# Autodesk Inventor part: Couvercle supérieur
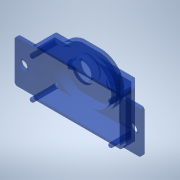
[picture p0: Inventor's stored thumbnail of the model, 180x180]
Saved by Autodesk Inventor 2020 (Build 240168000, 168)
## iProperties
Created: 2002-01
Part Number: Couvercle supérieur
Material: Polycarbonate, fumée
Document SubType Name: Modélisation
Designer: Philippe
Density: 1.2 g/cm^3
Appearance: Bleu (transparent)
Mass: 0.518225 g
Surface Area: 14.83 cm^2
Volume: 0.431854 cm^3
Control State: 0
Master: False
Checked Out: False
Shininess: 20.0
Angle Display Precision: 2
Document Length Units: 11269
Document Angle Units: 11279
Document Time Units: 11290
Document Mass Units: 11283
Document Length Units Precision: 3
Document Angle Units Precision: 2
Density: 0.0
Volumn: 0.0
Area: 0.0
PropertySet Name: Model Information
Author: Philippe
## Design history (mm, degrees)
sketch "Esquisse1"
  geometry: L1 (-1.506, 0)-(28.494, 0); L2 (28.494, 0)-(28.494, 0.8); L3 (28.494, 0.8)-(23.994, 0.8); L4 (23.994, 0.8)-(23.994, 5); L5 (23.994, 5)-(2.994, 5); L6 (2.994, 5)-(2.994, 0.8); L7 (2.994, 0.8)-(-1.506, 0.8); L8 (-1.506, 0.8)-(-1.506, 0); L9 (2.994, 0.8)-(2.994, 0); L10 (23.994, 0.8)-(23.994, 0)
  constraints: 20 end point, 8 parallel, 2 point on line, 1 collinear, 1 horizontal, 1 perpendicular, 1 other
  dimensions: "d0" = 4.5 distance of L2.end L3.end; "d1" = 4.5 distance of L6.end L7.end (= d0); "d2" = 30 distance of L1.start L1.end; "d3" = 0.8 distance between parallel lines of L3 L1; "d4" = 5 distance between parallel lines of L5 L1
extrude "Extrusion1" new body sketch "Esquisse1" stored distance "d5" = 11.4; taper "d6" = 0 deg
extrude "Extrusion2" join sketch "Esquisse1" stored distance "d7" = 10; taper "d8" = 0 deg
fillet "Congé1" dims "d9" = 0.6
fillet "Congé2" dims "d10" = 0.6
chamfer "Chanfrein1" distance "d11" = 2; stored, may be unused: second distance "d12" = 2, angle "d81" = 45 deg
sketch "Esquisse2"
  geometry: L1 (19, 10.8)-(0.6, 10.8) reference; L2 (0, 10.2)-(0, 0) reference; L3 (0.6, -0.6)-(19, -0.6) reference; A1 r 5.8 centre (5.8, 5.1) between (4.728, 10.8) and (4.728, -0.6); A2 r 5.7 centre (8.9, 5.1) between (8.9, -0.6) and (8.9, 10.8)
  constraints: 4 point on circle, 4 point on line, 3 tangent, 2 centre point, 1 horizontal alignment
  dimensions: "d13" = 5.8 radius of A1; "d14" = 14.6 dimension on A2 A1
extrude "Extrusion3" join sketch "Esquisse2" distance "d15" = 2.2; taper "d16" = 0 deg
fillet "Congé3" dims "d17" = 0.5
feature "Coque1" dims "d18" = 0.6, "d19" = 0.8
sketch "Esquisse3"
  geometry: C1 r 2.6 at (5.8, 5.1); A1 r 5.3 centre (5.8, 5.1) between (4.775, 10.3) and (4.775, -0.1) reference
  constraints: 1 centre point, 1 coincident
  dimensions: "d20" = 5.2 diameter of C1
extrude "Extrusion4" join sketch "Esquisse3" distance "d21" = 0.3; taper "d22" = 0 deg
sketch "Esquisse5"
  geometry: C1 r 2.6 at (1.015, -5.1); C2 r 2.6 at (1.015, -5.1) reference; A1 r 5.2 centre (1.015, -5.1) between (0, 0) and (0, -10.2) reference
  constraints: 1 centre point, 1 coincident, 1 concentric
extrude "Extrusion5" join sketch "Esquisse5" distance "d23" = 0.7; taper "d24" = 0 deg
sketch "Esquisse6"
  geometry: C1 r 2.6 at (0, 0) reference; 1 further point
  constraints: 1 coincident
hole "Perçage1" sketch "Esquisse6" at (0, 0), (0, 0) diameter "d25" = 4; stored, may be unused: countersink angle "d29" = 82 deg, drill point angle "d31" = 118 deg; dims "d26" = 6, "d27" = 4, "d28" = 2, "d30" = 8
sketch "Esquisse8"
  geometry: L1 (0, 11.4)-(0, 0) reference; L2 (-18.4, 0.6)-(1.4, 0.6) reference; L3 (1.4, 10.8)-(-18.4, 10.8) reference; L4 (-1, 0.6)-(-3.5, 0.6); L5 (-3.5, 0.6)-(-3.5, 10.8); L6 (-3.5, 10.8)-(-1, 10.8); L7 (-1, 10.8)-(-1, 0.6)
  constraints: 8 end point, 2 parallel, 2 point on line, 1 horizontal, 1 perpendicular
  dimensions: "d41" = 2.5 distance between parallel lines of L5 L7; "d42" = 1 distance between parallel lines of L1 L7
extrude "Extrusion6" cut sketch "Esquisse8" distance "d43" = 0.2; taper "d44" = 0 deg
sketch "Esquisse9"
  geometry: C1 r 2.6 at (1.015, -5.1) reference; C2 r 1 at (7.015, -5.1); C3 r 0.5 at (7.015, -5.1)
  constraints: 2 centre point, 1 coincident, 1 horizontal alignment
  dimensions: "d45" = 6 distance of C1.centre C2.centre; "d46" = 2 diameter of C2; "d47" = 1 diameter of C3
extrude "Extrusion7" join sketch "Esquisse9" distance "d48" = 0.3; taper "d49" = 0 deg
sketch "Esquisse10"
  geometry: L1 (4.115, -10.2)-(0, -10.2) reference; L2 (-2.076, -4.272)-(-0.917, -4.582); L3 (-2.076, -5.928)-(-1.497, -5.773); L4 (1.015, -5.1)-(-3.261, -5.1); L5 (-0.917, -4.582)-(-1.497, -4.427); L6 (-1.497, -5.773)-(-0.917, -5.618); A1 r 5.2 centre (1.015, -5.1) between (0, 0) and (0, -10.2) reference; A2 r 3.2 centre (1.015, -5.1) between (-2.076, -4.272) and (-2.076, -5.928); A3 r 2 centre (1.015, -5.1) between (-0.917, -4.582) and (-0.917, -5.618) reference; A4 r 2.6 centre (1.015, -5.1) between (-1.497, -5.773) and (-1.497, -4.427) reference; 1 further point
  constraints: 10 end point, 6 point on circle, 2 point on line, 1 centre point, 1 collinear, 1 concentric, 1 midpoint, 1 parallel, 3 other
  dimensions: "d50" = 3.2 radius of A2; "d51" = 30 deg angle of L3 L2
extrude "Extrusion8" join sketch "Esquisse10" distance "d52" = 1.2; taper "d53" = 0 deg
node "Plan de construction1"
sketch "Esquisse12"
  geometry: L1 (-0.6, -10.6)-(-0.6, -0.6) reference; L2 (20.4, -0.6)-(20.4, -10.6) reference; L3 (0, -11.4)-(19.8, -11.4) reference; L4 (19.8, 0)-(0, 0) reference; C1 r 0.5 at (0.6, -1.2); C2 r 0.5 at (0.6, -10.2); C3 r 0.5 at (19.2, -10.2); C4 r 0.5 at (19.2, -1.2)
  constraints: 4 centre point, 3 equal radius
  dimensions: "d58" = 1 diameter of C1; "d62" = 1.2 distance from line of L1 C2.centre; "d63" = 1.2 distance from line of L1 C1.centre; "d64" = 1.2 distance from line of L2 C3.centre; "d65" = 1.2 distance from line of L2 C4.centre; "d66" = 1.2 distance from line of C2.centre L3; "d67" = 1.2 distance from line of L3 C3.centre; "d68" = 1.2 distance from line of C4.centre L4; "d70" = 1.2 distance from line of C1.centre L4
extrude "Extrusion10" join sketch "Esquisse12" stored distance "d59" = 6.2; taper "d60" = 0 deg
fillet "Congé4" dims "d61" = 0.3
sketch "Esquisse13"
  geometry: L1 (24.9, -1.3)-(24.9, -10.1) reference; L2 (-5.1, -1.3)-(-5.1, -10.1) reference; A1 r 2 centre (5.2, -5.7) between (3.268, -6.218) and (3.268, -5.182) reference; 2 further points
  constraints: 2 horizontal alignment
  dimensions: "d72" = 2 distance from line of point (-3.1, -5.7) L2; "d73" = 2 distance from line of point (22.9, -5.7) L1
hole "Perçage3" sketch "Esquisse13" at (-3.1, -5.7), (22.9, -5.7) diameter "d74" = 2; stored, may be unused: countersink angle "d78" = 82 deg, drill point angle "d80" = 118 deg; dims "d75" = 6, "d76" = 4, "d77" = 2, "d79" = 8
node "Solide1"
node "Corps solides"
node "Corps surfaciques"
other parameters: "d57" = 1.8
